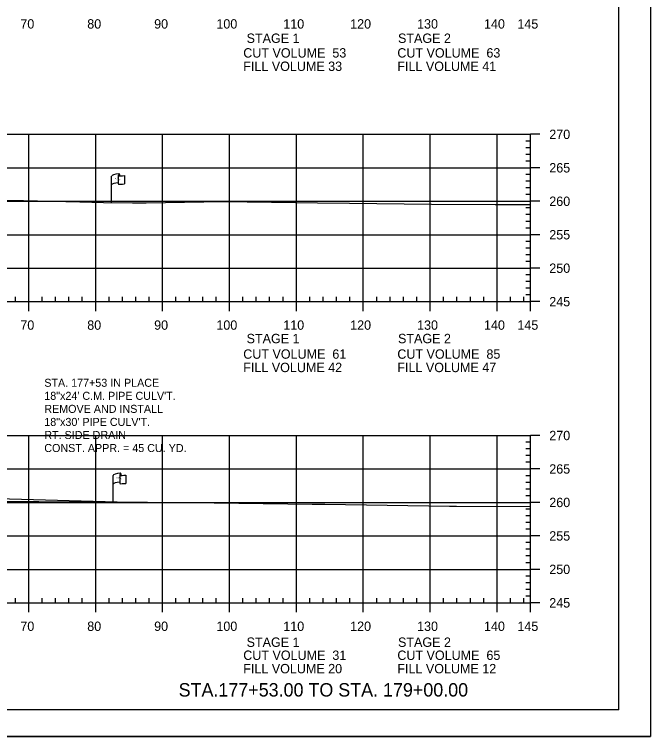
# Model space of a CAD drawing. Extents: x 1365647 to 1367999, y 387113 to 400173.
# Drawn here: x 1365961.9 to 1366057, y 387799.4 to 387907.3 of the extents above; entities that cross this region are included whole.
import ezdxf

# ---------------------------------------------------------------- set-up
doc = ezdxf.new("R2010")
doc.units = 0
for name, color, linetype in [('E_Existing ROW', 7, 'Continuous'), ('R_Axis', 7, 'Continuous'), ('R_Axis Annot', 7, 'Continuous'), ('R_Border', 7, 'Continuous'), ('R_Draft', 7, 'Continuous'), ('R_Drive', 7, 'Continuous'), ('R_Exist Surface', 7, 'Continuous'), ('R_Grid', 7, 'Continuous'), ('R_No Plot', 7, 'Continuous')]:
    doc.layers.add(name, color=color, linetype=linetype)

msp = doc.modelspace()

# ---------------------------------------------------------------- linework, layer by layer
at = {"layer": 'E_Existing ROW'}
for p, q in [((1365976.47, 387879.21), (1365976.47, 387883.16)), ((1365977.47, 387883.25), (1365977.47, 387883.24)), ((1365977.47, 387883.24), (1365977.47, 387882.01)), ((1365977.64, 387883.41), (1365977.64, 387883.17)), ((1365978.41, 387883.22), (1365978.41, 387881.98)), ((1365976.69, 387834.47), (1365976.69, 387838.42)), ((1365977.69, 387838.51), (1365977.69, 387838.5)), ((1365977.69, 387838.5), (1365977.69, 387837.27)), ((1365977.86, 387838.67), (1365977.86, 387838.43)), ((1365978.62, 387838.48), (1365978.62, 387837.24))]:
    msp.add_line(p, q, dxfattribs=at)
for centre, radius, start, end in [((1365977.55, 387883.25), 0.078, 88.6458, 274.2828), ((1365977.56, 387883.41), 0.0783, 263.0712, 93.9564), ((1365977.55, 387882.01), 0.0783, 180, 273.9564), ((1365977.77, 387838.51), 0.078, 88.6458, 274.2828), ((1365977.78, 387838.67), 0.0783, 263.0712, 93.9564), ((1365977.77, 387837.27), 0.0783, 180, 273.9564)]:
    msp.add_arc(centre, radius, start, end, dxfattribs=at)
for centre, major_axis, ratio, start_param, end_param in [((1365978.06, 387883.2), (-1.58, -0.04), 0.19887, 5.030368, 6.283185), ((1365978.76, 387883.32), (-1.23, -0.13), 0.052933, 0.159456, 1.268315), ((1365978.05, 387881.88), (-1.58, -0.04), 0.19887, 5.083035, 6.194897), ((1365978.76, 387882.08), (-1.23, -0.13), 0.052933, 0.159456, 1.268315), ((1365978.28, 387838.46), (-1.58, -0.04), 0.19887, 5.030368, 6.283185), ((1365978.98, 387838.58), (-1.23, -0.13), 0.052933, 0.159456, 1.268315), ((1365978.27, 387837.14), (-1.58, -0.04), 0.19887, 5.083035, 6.194897), ((1365978.98, 387837.34), (-1.23, -0.13), 0.052933, 0.159456, 1.268315)]:
    msp.add_ellipse(centre, major_axis=major_axis, ratio=ratio, start_param=start_param, end_param=end_param, dxfattribs=at)
at = {"layer": 'R_Axis'}
for p, q in [((1366039.09, 387864.39), (1366039.09, 387889.39)), ((1366040.49, 387889.39), (1366039.09, 387889.39)), ((1366039.09, 387888.39), (1366038.39, 387888.39)), ((1366039.09, 387887.39), (1366038.39, 387887.39)), ((1366039.09, 387886.39), (1366038.39, 387886.39)), ((1366039.09, 387885.39), (1366038.39, 387885.39)), ((1366040.49, 387884.39), (1366039.09, 387884.39)), ((1366039.09, 387883.39), (1366038.39, 387883.39)), ((1366039.09, 387882.39), (1366038.39, 387882.39)), ((1366039.09, 387881.39), (1366038.39, 387881.39)), ((1366039.09, 387880.39), (1366038.39, 387880.39)), ((1366040.49, 387879.39), (1366039.09, 387879.39)), ((1366039.09, 387878.39), (1366038.39, 387878.39)), ((1366039.09, 387877.39), (1366038.39, 387877.39)), ((1366039.09, 387876.39), (1366038.39, 387876.39)), ((1366039.09, 387875.39), (1366038.39, 387875.39)), ((1366040.49, 387874.39), (1366039.09, 387874.39)), ((1366039.09, 387873.39), (1366038.39, 387873.39)), ((1366039.09, 387872.39), (1366038.39, 387872.39)), ((1366039.09, 387871.39), (1366038.39, 387871.39)), ((1366039.09, 387870.39), (1366038.39, 387870.39)), ((1366040.49, 387869.39), (1366039.09, 387869.39)), ((1366039.09, 387868.39), (1366038.39, 387868.39)), ((1366039.09, 387867.39), (1366038.39, 387867.39)), ((1366039.09, 387866.39), (1366038.39, 387866.39)), ((1365962.09, 387864.39), (1365962.09, 387865.09)), ((1365966.09, 387864.39), (1365966.09, 387865.09)), ((1365968.09, 387864.39), (1365968.09, 387865.09)), ((1365970.09, 387864.39), (1365970.09, 387865.09)), ((1365972.09, 387864.39), (1365972.09, 387865.09)), ((1365976.09, 387864.39), (1365976.09, 387865.09)), ((1365978.09, 387864.39), (1365978.09, 387865.09)), ((1365980.09, 387864.39), (1365980.09, 387865.09)), ((1365982.09, 387864.39), (1365982.09, 387865.09)), ((1365986.09, 387864.39), (1365986.09, 387865.09)), ((1365988.09, 387864.39), (1365988.09, 387865.09)), ((1365990.09, 387864.39), (1365990.09, 387865.09)), ((1365992.09, 387864.39), (1365992.09, 387865.09)), ((1365996.09, 387864.39), (1365996.09, 387865.09)), ((1365998.09, 387864.39), (1365998.09, 387865.09)), ((1366000.09, 387864.39), (1366000.09, 387865.09)), ((1366002.09, 387864.39), (1366002.09, 387865.09)), ((1366006.09, 387864.39), (1366006.09, 387865.09)), ((1366008.09, 387864.39), (1366008.09, 387865.09)), ((1366010.09, 387864.39), (1366010.09, 387865.09)), ((1366012.09, 387864.39), (1366012.09, 387865.09)), ((1366016.09, 387864.39), (1366016.09, 387865.09)), ((1366018.09, 387864.39), (1366018.09, 387865.09)), ((1366020.09, 387864.39), (1366020.09, 387865.09)), ((1366022.09, 387864.39), (1366022.09, 387865.09)), ((1366026.09, 387864.39), (1366026.09, 387865.09)), ((1366028.09, 387864.39), (1366028.09, 387865.09)), ((1366030.09, 387864.39), (1366030.09, 387865.09)), ((1366032.09, 387864.39), (1366032.09, 387865.09)), ((1366036.09, 387864.39), (1366036.09, 387865.09)), ((1366038.09, 387864.39), (1366038.09, 387865.09)), ((1366039.09, 387865.39), (1366038.39, 387865.39)), ((1365749.09, 387864.39), (1366039.09, 387864.39)), ((1365964.09, 387862.99), (1365964.09, 387864.39)), ((1365974.09, 387862.99), (1365974.09, 387864.39)), ((1365984.09, 387862.99), (1365984.09, 387864.39)), ((1365994.09, 387862.99), (1365994.09, 387864.39)), ((1366004.09, 387862.99), (1366004.09, 387864.39)), ((1366014.09, 387862.99), (1366014.09, 387864.39)), ((1366024.09, 387862.99), (1366024.09, 387864.39)), ((1366034.09, 387862.99), (1366034.09, 387864.39)), ((1366039.09, 387862.99), (1366039.09, 387864.39)), ((1366040.49, 387864.39), (1366039.09, 387864.39)), ((1366039.09, 387819.39), (1366039.09, 387844.39)), ((1366040.49, 387844.39), (1366039.09, 387844.39)), ((1366039.09, 387843.39), (1366038.39, 387843.39)), ((1366039.09, 387842.39), (1366038.39, 387842.39)), ((1366039.09, 387841.39), (1366038.39, 387841.39)), ((1366039.09, 387840.39), (1366038.39, 387840.39)), ((1366040.49, 387839.39), (1366039.09, 387839.39)), ((1366039.09, 387838.39), (1366038.39, 387838.39)), ((1366039.09, 387837.39), (1366038.39, 387837.39)), ((1366039.09, 387836.39), (1366038.39, 387836.39)), ((1366039.09, 387835.39), (1366038.39, 387835.39)), ((1366040.49, 387834.39), (1366039.09, 387834.39)), ((1366039.09, 387833.39), (1366038.39, 387833.39)), ((1366039.09, 387832.39), (1366038.39, 387832.39)), ((1366039.09, 387831.39), (1366038.39, 387831.39)), ((1366039.09, 387830.39), (1366038.39, 387830.39)), ((1366040.49, 387829.39), (1366039.09, 387829.39)), ((1366039.09, 387828.39), (1366038.39, 387828.39)), ((1366039.09, 387827.39), (1366038.39, 387827.39)), ((1366039.09, 387826.39), (1366038.39, 387826.39)), ((1366039.09, 387825.39), (1366038.39, 387825.39)), ((1366040.49, 387824.39), (1366039.09, 387824.39)), ((1366039.09, 387823.39), (1366038.39, 387823.39)), ((1366039.09, 387822.39), (1366038.39, 387822.39)), ((1366039.09, 387821.39), (1366038.39, 387821.39)), ((1365962.09, 387819.39), (1365962.09, 387820.09)), ((1365966.09, 387819.39), (1365966.09, 387820.09)), ((1365968.09, 387819.39), (1365968.09, 387820.09)), ((1365970.09, 387819.39), (1365970.09, 387820.09)), ((1365972.09, 387819.39), (1365972.09, 387820.09)), ((1365976.09, 387819.39), (1365976.09, 387820.09)), ((1365978.09, 387819.39), (1365978.09, 387820.09)), ((1365980.09, 387819.39), (1365980.09, 387820.09)), ((1365982.09, 387819.39), (1365982.09, 387820.09)), ((1365986.09, 387819.39), (1365986.09, 387820.09)), ((1365988.09, 387819.39), (1365988.09, 387820.09)), ((1365990.09, 387819.39), (1365990.09, 387820.09)), ((1365992.09, 387819.39), (1365992.09, 387820.09)), ((1365996.09, 387819.39), (1365996.09, 387820.09)), ((1365998.09, 387819.39), (1365998.09, 387820.09)), ((1366000.09, 387819.39), (1366000.09, 387820.09)), ((1366002.09, 387819.39), (1366002.09, 387820.09)), ((1366006.09, 387819.39), (1366006.09, 387820.09)), ((1366008.09, 387819.39), (1366008.09, 387820.09)), ((1366010.09, 387819.39), (1366010.09, 387820.09)), ((1366012.09, 387819.39), (1366012.09, 387820.09)), ((1366016.09, 387819.39), (1366016.09, 387820.09)), ((1366018.09, 387819.39), (1366018.09, 387820.09)), ((1366020.09, 387819.39), (1366020.09, 387820.09)), ((1366022.09, 387819.39), (1366022.09, 387820.09)), ((1366026.09, 387819.39), (1366026.09, 387820.09)), ((1366028.09, 387819.39), (1366028.09, 387820.09)), ((1366030.09, 387819.39), (1366030.09, 387820.09)), ((1366032.09, 387819.39), (1366032.09, 387820.09)), ((1366036.09, 387819.39), (1366036.09, 387820.09)), ((1366038.09, 387819.39), (1366038.09, 387820.09)), ((1366039.09, 387820.39), (1366038.39, 387820.39)), ((1365749.09, 387819.39), (1366039.09, 387819.39)), ((1365964.09, 387817.99), (1365964.09, 387819.39)), ((1365974.09, 387817.99), (1365974.09, 387819.39)), ((1365984.09, 387817.99), (1365984.09, 387819.39)), ((1365994.09, 387817.99), (1365994.09, 387819.39)), ((1366004.09, 387817.99), (1366004.09, 387819.39)), ((1366014.09, 387817.99), (1366014.09, 387819.39)), ((1366024.09, 387817.99), (1366024.09, 387819.39)), ((1366034.09, 387817.99), (1366034.09, 387819.39)), ((1366039.09, 387817.99), (1366039.09, 387819.39)), ((1366040.49, 387819.39), (1366039.09, 387819.39))]:
    msp.add_line(p, q, dxfattribs=at)
at = {"layer": 'R_Border'}
for q in [(1366052.27, 388008.85), (1365736.09, 387803.39)]:
    msp.add_line((1366052.27, 387803.39), q, dxfattribs=at)
at = {"layer": 'R_Drive'}
msp.add_line((1365938.56, 387835.49), (1365979.09, 387834.45), dxfattribs=at)
at = {"layer": 'R_Exist Surface'}
for points in [[(1365958.24, 387879.5), (1365963.29, 387879.52), (1365971.74, 387879.31), (1365975.27, 387879.22), (1365979.58, 387879.17), (1365981.62, 387879.18), (1365993.14, 387879.35), (1366003.98, 387879.2), (1366007.24, 387879.16), (1366012.02, 387879.13), (1366024.26, 387878.97), (1366033.79, 387878.93), (1366039.09, 387878.9)], [(1365960.33, 387834.59), (1365970.89, 387834.49), (1365976.35, 387834.47), (1365987.34, 387834.39), (1365987.65, 387834.39), (1365988.17, 387834.39), (1366006.47, 387834.13), (1366007.67, 387834.12), (1366008.33, 387834.11), (1366026.98, 387833.84), (1366028.02, 387833.83), (1366039.09, 387833.77)]]:
    msp.add_lwpolyline(points, dxfattribs=at)
at = {"layer": 'R_Grid'}
for p, q in [((1365749.09, 387889.39), (1366039.09, 387889.39)), ((1365964.09, 387864.39), (1365964.09, 387889.39)), ((1365974.09, 387864.39), (1365974.09, 387889.39)), ((1365984.09, 387864.39), (1365984.09, 387889.39)), ((1365994.09, 387864.39), (1365994.09, 387889.39)), ((1366004.09, 387864.39), (1366004.09, 387889.39)), ((1366014.09, 387864.39), (1366014.09, 387889.39)), ((1366024.09, 387864.39), (1366024.09, 387889.39)), ((1366034.09, 387864.39), (1366034.09, 387889.39)), ((1366039.09, 387864.39), (1366039.09, 387889.39)), ((1365749.09, 387884.39), (1366039.09, 387884.39)), ((1365749.09, 387879.39), (1366039.09, 387879.39)), ((1365749.09, 387874.39), (1366039.09, 387874.39)), ((1365749.09, 387869.39), (1366039.09, 387869.39)), ((1365749.09, 387864.39), (1366039.09, 387864.39)), ((1365749.09, 387844.39), (1366039.09, 387844.39)), ((1365964.09, 387819.39), (1365964.09, 387844.39)), ((1365974.09, 387819.39), (1365974.09, 387844.39)), ((1365984.09, 387819.39), (1365984.09, 387844.39)), ((1365994.09, 387819.39), (1365994.09, 387844.39)), ((1366004.09, 387819.39), (1366004.09, 387844.39)), ((1366014.09, 387819.39), (1366014.09, 387844.39)), ((1366024.09, 387819.39), (1366024.09, 387844.39)), ((1366034.09, 387819.39), (1366034.09, 387844.39)), ((1366039.09, 387819.39), (1366039.09, 387844.39)), ((1365749.09, 387839.39), (1366039.09, 387839.39)), ((1365749.09, 387834.39), (1366039.09, 387834.39)), ((1365749.09, 387829.39), (1366039.09, 387829.39)), ((1365749.09, 387824.39), (1366039.09, 387824.39)), ((1365749.09, 387819.39), (1366039.09, 387819.39))]:
    msp.add_line(p, q, dxfattribs=at)
at = {"layer": 'R_No Plot'}
msp.add_line((1365723.69, 387799.41), (1366057.03, 387799.41), dxfattribs=at)
msp.add_lwpolyline([(1365723.69, 388012.75), (1366057.03, 388012.75), (1366057.03, 387799.41), (1365723.69, 387799.41)], close=True, dxfattribs=at)

# ---------------------------------------------------------------- texts
at = {"layer": 'E_Existing ROW'}
for s, height, rotation, p in [('DWB 11-9-07', 0.001, 90, (1365977.64, 387883.17)), ('R ', 0.2, 9.9884, (1365976.99, 387882.66)), (' O', 0.2, 9.9884, (1365977.14, 387882.71)), ('W', 0.2, 351.1788, (1365977.47, 387882.54)), ('DWB 11-9-07', 0.001, 5.0717, (1365978.4, 387881.98)), ('DWB 11-9-07', 0.001, 90, (1365976.47, 387879.21)), ('R ', 0.2, 9.9884, (1365977.21, 387837.92)), (' O', 0.2, 9.9884, (1365977.36, 387837.97)), ('W', 0.2, 351.1788, (1365977.69, 387837.8)), ('DWB 11-9-07', 0.001, 90, (1365977.86, 387838.43)), ('DWB 11-9-07', 0.001, 5.0717, (1365978.61, 387837.24)), ('DWB 11-9-07', 0.001, 90, (1365976.69, 387834.47))]:
    msp.add_text(s, height=height, rotation=rotation, dxfattribs=at).set_placement(p)
at = {"layer": 'R_Axis Annot'}
for s, p in [('70', (1365962.83, 387905.19)), ('80', (1365972.83, 387905.19)), ('90', (1365982.83, 387905.19)), ('100', (1365992.13, 387905.19)), ('110', (1366002.13, 387905.19)), ('120', (1366012.13, 387905.19)), ('130', (1366022.13, 387905.19)), ('140', (1366032.13, 387905.19)), ('145', (1366037.12, 387905.19)), ('STAGE 1', (1365996.65, 387903.05)), ('STAGE 2', (1366019.28, 387903.05)), ('CUT VOLUME  53', (1365996.15, 387900.86)), ('CUT VOLUME  63', (1366019.18, 387900.86)), ('FILL VOLUME 33', (1365996.15, 387898.86)), ('FILL VOLUME 41', (1366019.18, 387898.86)), ('270', (1366041.89, 387888.69)), ('265', (1366041.89, 387883.69)), ('260', (1366041.89, 387878.69)), ('255', (1366041.89, 387873.69)), ('250', (1366041.89, 387868.69)), ('245', (1366041.89, 387863.69)), ('70', (1365962.83, 387860.19)), ('80', (1365972.83, 387860.19)), ('90', (1365982.83, 387860.19)), ('100', (1365992.13, 387860.19)), ('110', (1366002.13, 387860.19)), ('120', (1366012.13, 387860.19)), ('130', (1366022.13, 387860.19)), ('140', (1366032.13, 387860.19)), ('145', (1366037.12, 387860.19)), ('STAGE 1', (1365996.65, 387858.18)), ('STAGE 2', (1366019.28, 387858.18)), ('CUT VOLUME  61', (1365996.15, 387855.86)), ('CUT VOLUME  85', (1366019.18, 387855.86)), ('FILL VOLUME 42', (1365996.15, 387853.86)), ('FILL VOLUME 47', (1366019.18, 387853.86)), ('270', (1366041.89, 387843.69)), ('265', (1366041.89, 387838.69)), ('260', (1366041.89, 387833.69)), ('255', (1366041.89, 387828.69)), ('250', (1366041.89, 387823.69)), ('245', (1366041.89, 387818.69)), ('70', (1365962.83, 387815.19)), ('80', (1365972.83, 387815.19)), ('90', (1365982.83, 387815.19)), ('100', (1365992.13, 387815.19)), ('110', (1366002.13, 387815.19)), ('120', (1366012.13, 387815.19)), ('130', (1366022.13, 387815.19)), ('140', (1366032.13, 387815.19)), ('145', (1366037.12, 387815.19)), ('STAGE 1', (1365996.65, 387812.81)), ('STAGE 2', (1366019.28, 387812.81)), ('CUT VOLUME  31', (1365996.15, 387810.86)), ('CUT VOLUME  65', (1366019.18, 387810.86)), ('FILL VOLUME 20', (1365996.15, 387808.86)), ('FILL VOLUME 12', (1366019.18, 387808.86))]:
    msp.add_text(s, height=1.4, dxfattribs=at).set_placement(p)
at = {"layer": 'R_Draft'}
for s, p in [('STA. 177+53 IN PLACE', (1365966.41, 387851.67)), ('18"x24\' C.M. PIPE CULV\'T.', (1365966.41, 387849.72)), ('REMOVE AND INSTALL ', (1365966.41, 387847.77)), ('18"x30\' PIPE CULV\'T.', (1365966.41, 387845.82)), ('RT. SIDE DRAIN', (1365966.41, 387843.87)), ('CONST. APPR. = 45 CU. YD.', (1365966.41, 387841.92))]:
    msp.add_text(s, height=1.2, rotation=360, dxfattribs=at).set_placement(p)
msp.add_text('STA.177+53.00 TO STA. 179+00.00', height=2, dxfattribs=at).set_placement((1365986.49, 387805.39))

doc.saveas('drawing.dxf')
